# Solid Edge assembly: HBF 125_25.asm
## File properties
Title: Zylinder
Author: ahadarics
Template: iso assembly.asm
Last saved by: ahadarics
Revision: 14
Application: Solid Edge
Username: ahadarics
Dokumentum tartalom típus: 1
Document Number: HBF 125/25
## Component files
Profilrohr 125_25.par
Kit.par
Kolbenstange_1_125_25.par
Mutter.par
Kolbenstange_2_125_25.par
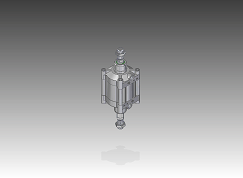
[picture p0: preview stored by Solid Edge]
